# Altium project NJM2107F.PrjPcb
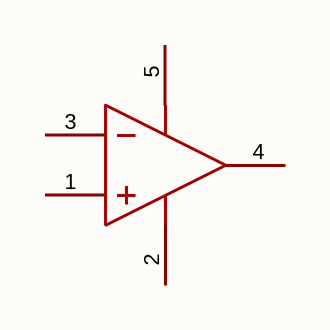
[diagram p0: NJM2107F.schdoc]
1 sheet, 1 parts. Net scope: global (net labels, ports and power ports of the same name join across sheets).

## Sheet NJM2107F.schdoc
size 127 x 101 mm

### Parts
U?  njm2107f  [SOT-23-5_L2.9-W1.6-P0.95-LS2.8-BR]  (value not drawn)

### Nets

Not connected (* = marked no-connect by the designer): U? 1(+INPUT) 2(V-) 3(-INPUT) 4(OUTPUT) 5(V+)

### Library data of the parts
U? = njm2107f: 放大器数:1;轨到轨:-;增益带宽积(GBW):-;输入失调电压(Vos):6mV;压摆率(SR):3V/us;输入偏置电流(Ib):500nA;; Manufacturer: TECH PUBLIC(台舟); AddInBom: yes; ModelId: 7ba65df16e7b4570af156e925f9c37fe; ModelTransform: 114.173,114.173,0,90,0,0,0,0,0; Number of Channels: 1; Vos - Input Offset Voltage: 6mV; Slew Rate: 3V/us; Ib - Input Bias Current: 500nA; Input Offset Current(Ios): 5nA; Common Mode Rejection Ratio(CMRR): 80dB; Quiescent Current: 2mA; Single supply: 1V~3.5V; Dual Supply: -3.5V~3.5V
